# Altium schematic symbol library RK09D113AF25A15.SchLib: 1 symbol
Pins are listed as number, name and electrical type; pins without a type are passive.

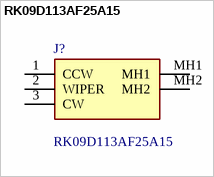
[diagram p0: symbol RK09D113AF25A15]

## RK09D113AF25A15
designator J?
Potentiometers; Manufacturer_Name: ALPS Electric; Geometry.Height: 25mm
footprint RK09D113AF25A15
pins: 1 CCW, 2 WIPER, 3 CW, MH1, MH2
